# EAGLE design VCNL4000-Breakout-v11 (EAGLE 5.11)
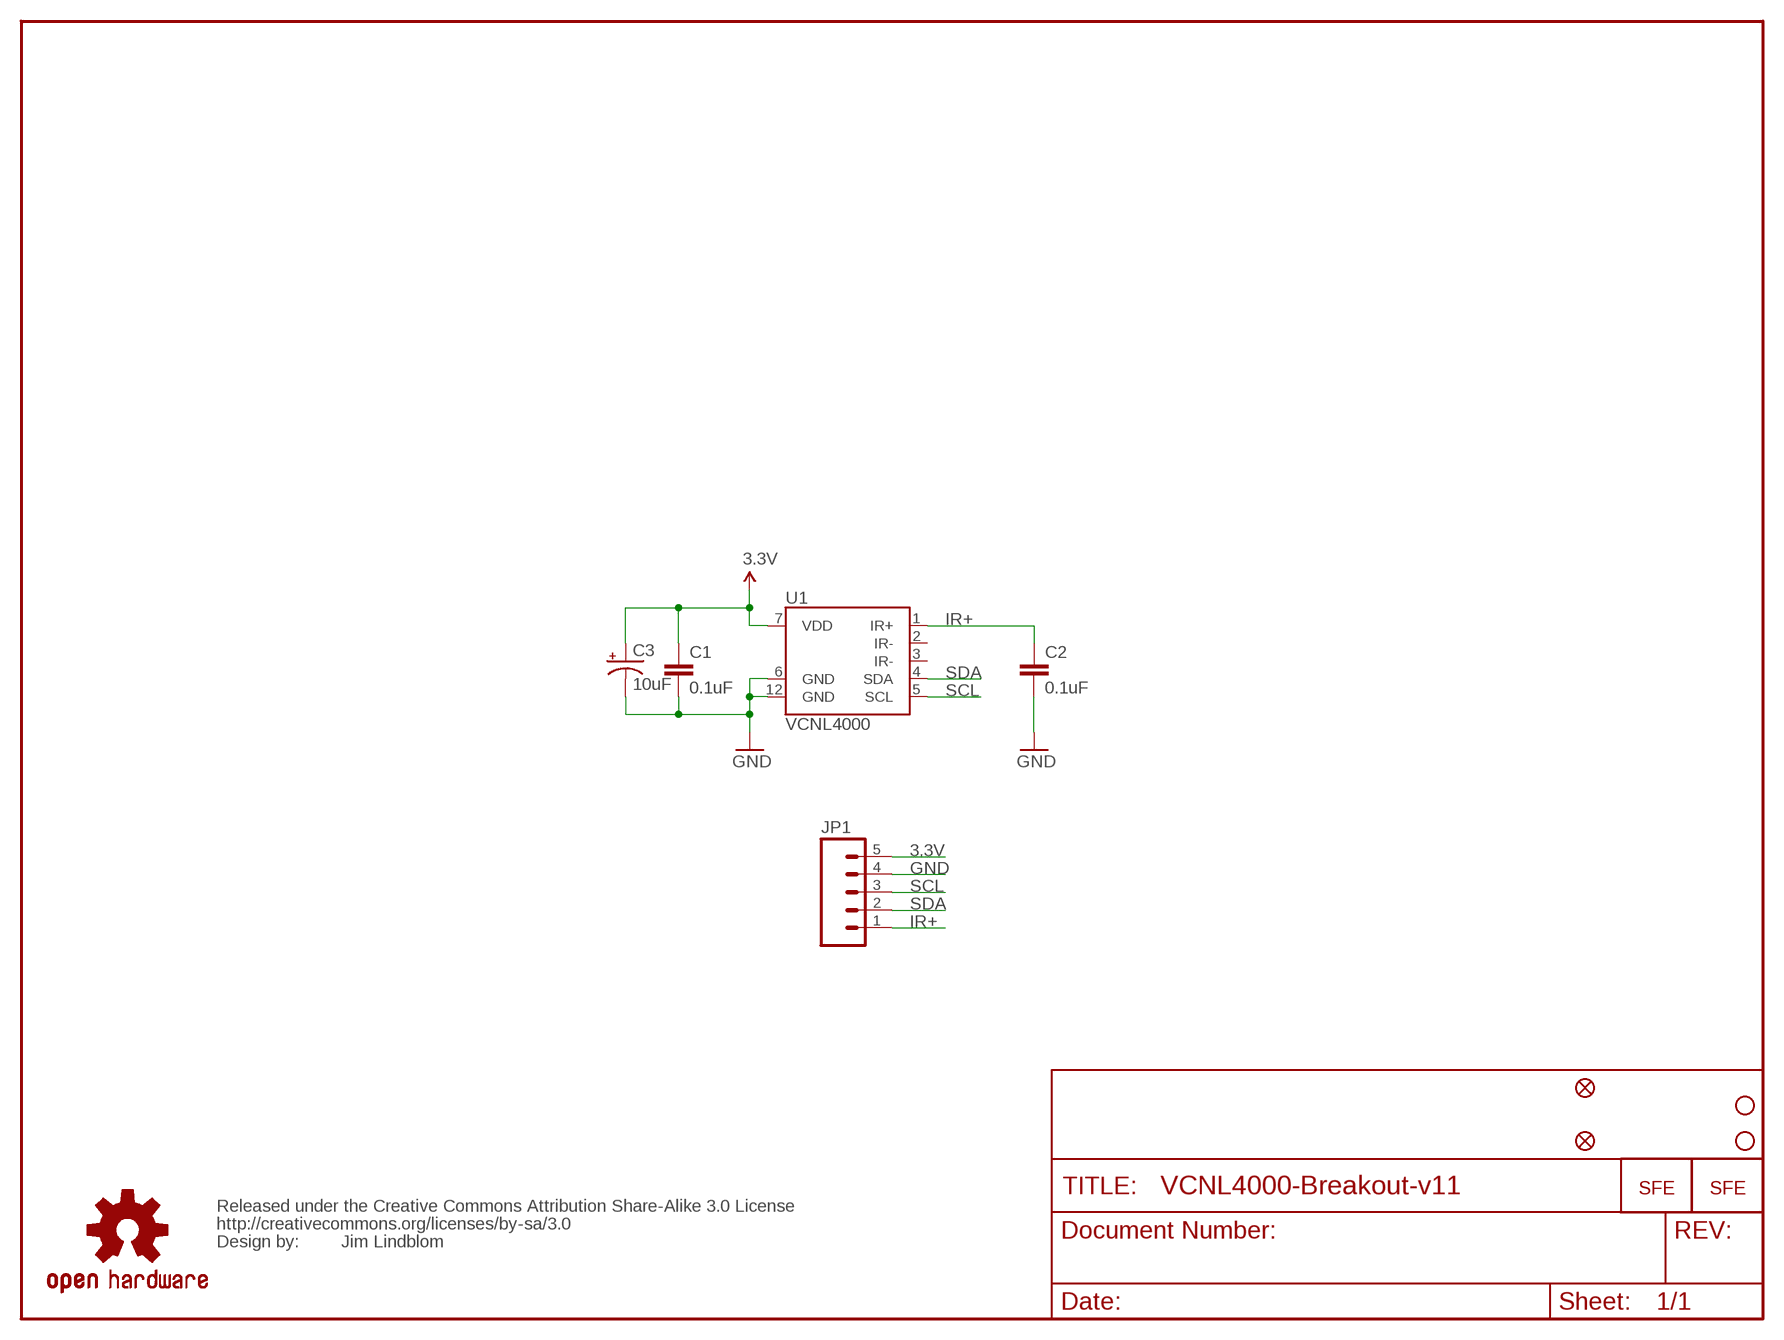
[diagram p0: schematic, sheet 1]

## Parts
C1  0.1uF  CAP0402-CAP  [0402-CAP]
C2  0.1uF  CAP0402-CAP  [0402-CAP]
C3  10uF  CAP_POL1206  [EIA3216]
JP1  M05PTH  [1X05]
JP2  LOGO-SFENW2  [SFE-NEW-WEB]
JP3  STAND-OFF  [STAND-OFF]
JP4  STAND-OFF  [STAND-OFF]
JP5  LOGO-SFESK  [SFE-LOGO-FLAME]
JP6  FIDUCIALUFIDUCIAL  [MICRO-FIDUCIAL]
JP7  FIDUCIALUFIDUCIAL  [MICRO-FIDUCIAL]
U1  VCNL4000  [VCNL4000]
U$1  OSHW-LOGOS  [OSHW-LOGO-S]
U$2  CREATIVE_COMMONS  [CREATIVE_COMMONS]

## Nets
3.3V: C1.1 C3.A(+) JP1.5 U1.7(VDD)
GND: C1.2 C2.2 C3.C(-) JP1.4 U1.6(GND) U1.12(GND)
IR+: C2.1 JP1.1 U1.1(IR+)
SCL: JP1.3 U1.5(SCL)
SDA: JP1.2 U1.4(SDA)
Unconnected: U1.2(IR-) U1.3(IR-)

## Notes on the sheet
- Jim Lindblom

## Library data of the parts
C1 C2 = SparkFun:CAP: Capacitor
C3 = SparkFun:CAP_POL: Capacitor Polarized
JP1 = SparkFun:M05: Header 5 Standard 5-pin 0.1" header. Use with straight break away headers (SKU : PRT-00116), right angle break away headers (PRT-00553), swiss pins (PRT-00743), machine pins (PRT-00117), and female headers (PRT-00115). Molex polarized connector foot print use with SKU : PRT-08230 with associated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
JP2 JP5 = SparkFun:LOGO-SFE: Spark Fun Electronics PCB Logo
JP3 JP4 = SparkFun:STAND-OFF: Stand Off
JP6 JP7 = SparkFun:FIDUCIAL: Fiducial Alignment Points
U1 = SparkFun:VCNL4000: VNCL4000 Fully integrated proximity and ambient light sensor with infrared emitter and I2C interface
U$1 = SparkFun:OSHW-LOGO: Open Source Hardware Logo This logo indicates the piece of hardware it is found on incorporates a OSHW license and/or adheres to the definition of open source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
U$2 = SparkFun:CREATIVE_COMMONS

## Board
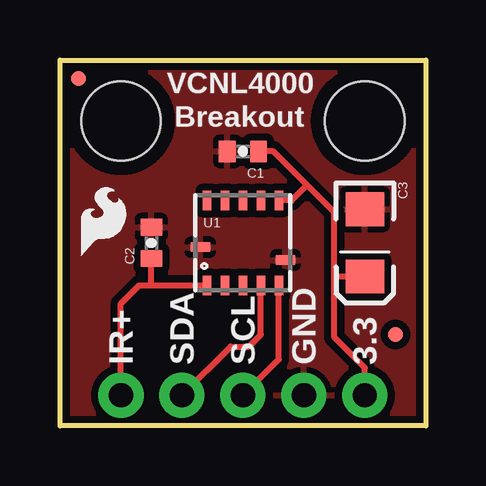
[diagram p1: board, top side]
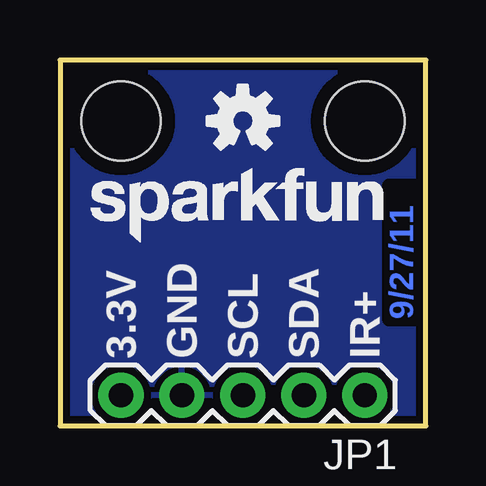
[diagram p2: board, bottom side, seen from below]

Size 15.24 x 15.24 mm. Coordinates in mm from the lower left corner, seen from the top.
Outline: 0,0 0,15.24 15.24,15.24 15.24,0 0,0
Copper layers (1*16): Top 0.035mm / dielectric 1.5mm / Bottom 0.035mm
Design rules "SparkFun": minimum track width 8mil, minimum drill 20mil, track to track 8mil, track to pad 8mil, pad to pad 8mil, via to via 8mil, smd to smd 8mil, copper to edge 8mil, drill to drill 8mil, minimum pad ring 12mil, minimum via ring 10mil, stop-mask expansion 4mil, vias tented up to drill 20mil, thermal gap 10mil

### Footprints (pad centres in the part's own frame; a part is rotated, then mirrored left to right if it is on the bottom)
0402-CAP = smd 0.7 x 0.9: 1 -0.65,0; 2 0.65,0
EIA3216 = smd 1.4 x 1.6: A 1.4,0; C -1.4,0
1X05 = drill 1.016 pad 1.88 round: 1 0,0; 2 2.54,0; 3 5.08,0; 4 7.62,0; 5 10.16,0
STAND-OFF = hole 3.302: 0,0
MICRO-FIDUCIAL = smd 0.635 x 0.635: 1 0,0
VCNL4000 = smd 0.35 x 0.805: 1 -1.5,-1.772; 2 -0.75,-1.772; 3 0,-1.772; 4 0.75,-1.772; 5 1.5,-1.772; 7 1.5,1.772; 8 0.75,1.772; 9 0,1.772; 10 -0.75,1.772; 11 -1.5,1.772 | smd 0.805 x 0.4: 6 1.772,-0.715; 12 -1.772,-0.175

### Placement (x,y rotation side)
C1  7.62,11.43 180 top
C2  3.81,7.62 90 top
C3  12.7,7.62 270 top
JP1  2.54,1.27 180 bottom
JP2  13.97,7.62 0 bottom
JP3  2.54,12.7 0 top
JP4  12.7,12.7 0 top
JP5  0.89,7.11 0 top
JP6  13.97,3.81 0 top
JP7  0.76,14.48 0 top
U1  7.62,7.62 0 top
U$1  7.62,12.7 0 bottom
U$2  not placed on the board

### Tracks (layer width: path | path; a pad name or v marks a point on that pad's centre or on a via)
3.3V
  Top 0.254: JP1.5 12.7,2.41 11.43,3.68 11.43,6.22 | C1.1 8.89,11.43 10.35,9.97 | U1.7 9.66,9.39 10.23,9.97 10.35,9.97 | C3.A 11.43,6.22 | 10.35,9.97 11.43,8.89 11.43,6.22
GND
  pour Bottom (isolate 0.305): 0,0 0,15.24 15.24,15.24 15.24,0
  pour Top (isolate 0.305): 0,0 0,15.24 15.24,15.24 15.24,0
IR+
  Top 0.254: 3.81,5.85 3.31,5.85 2.54,5.08 JP1.1 | 3.81,5.85 U1.1 | 3.81,5.85 C2.1
SCL
  Top 0.254: U1.5 9.12,2.77 JP1.3
SDA
  Top 0.254: U1.4 8.37,3.8 7.87,3.3 7.11,3.3 JP1.2

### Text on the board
Bottom: 9/27/11
tPlace: VCNL4000 | Breakout | IR+ | SDA | SCL | GND | 3.3
bPlace: IR+ | SDA | SCL | GND | 3.3V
